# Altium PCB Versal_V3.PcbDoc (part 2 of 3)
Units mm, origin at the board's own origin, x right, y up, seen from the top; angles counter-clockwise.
Board outline 164.5 x 88.9 mm, 8 copper layers (Top Layer, Layer 2 [GND], Layer 3 [GND/OUT], Layer 4 [12V/GND], Layer 5 [GND/VOUT], Layer 6 [GND], Layer 7 [GND], Bottom Layer), stack 1.562 mm thick; 243 components, 69 nets, 695 pads, 1061 vias.
Unrouted connection lines stored in the file: 8.
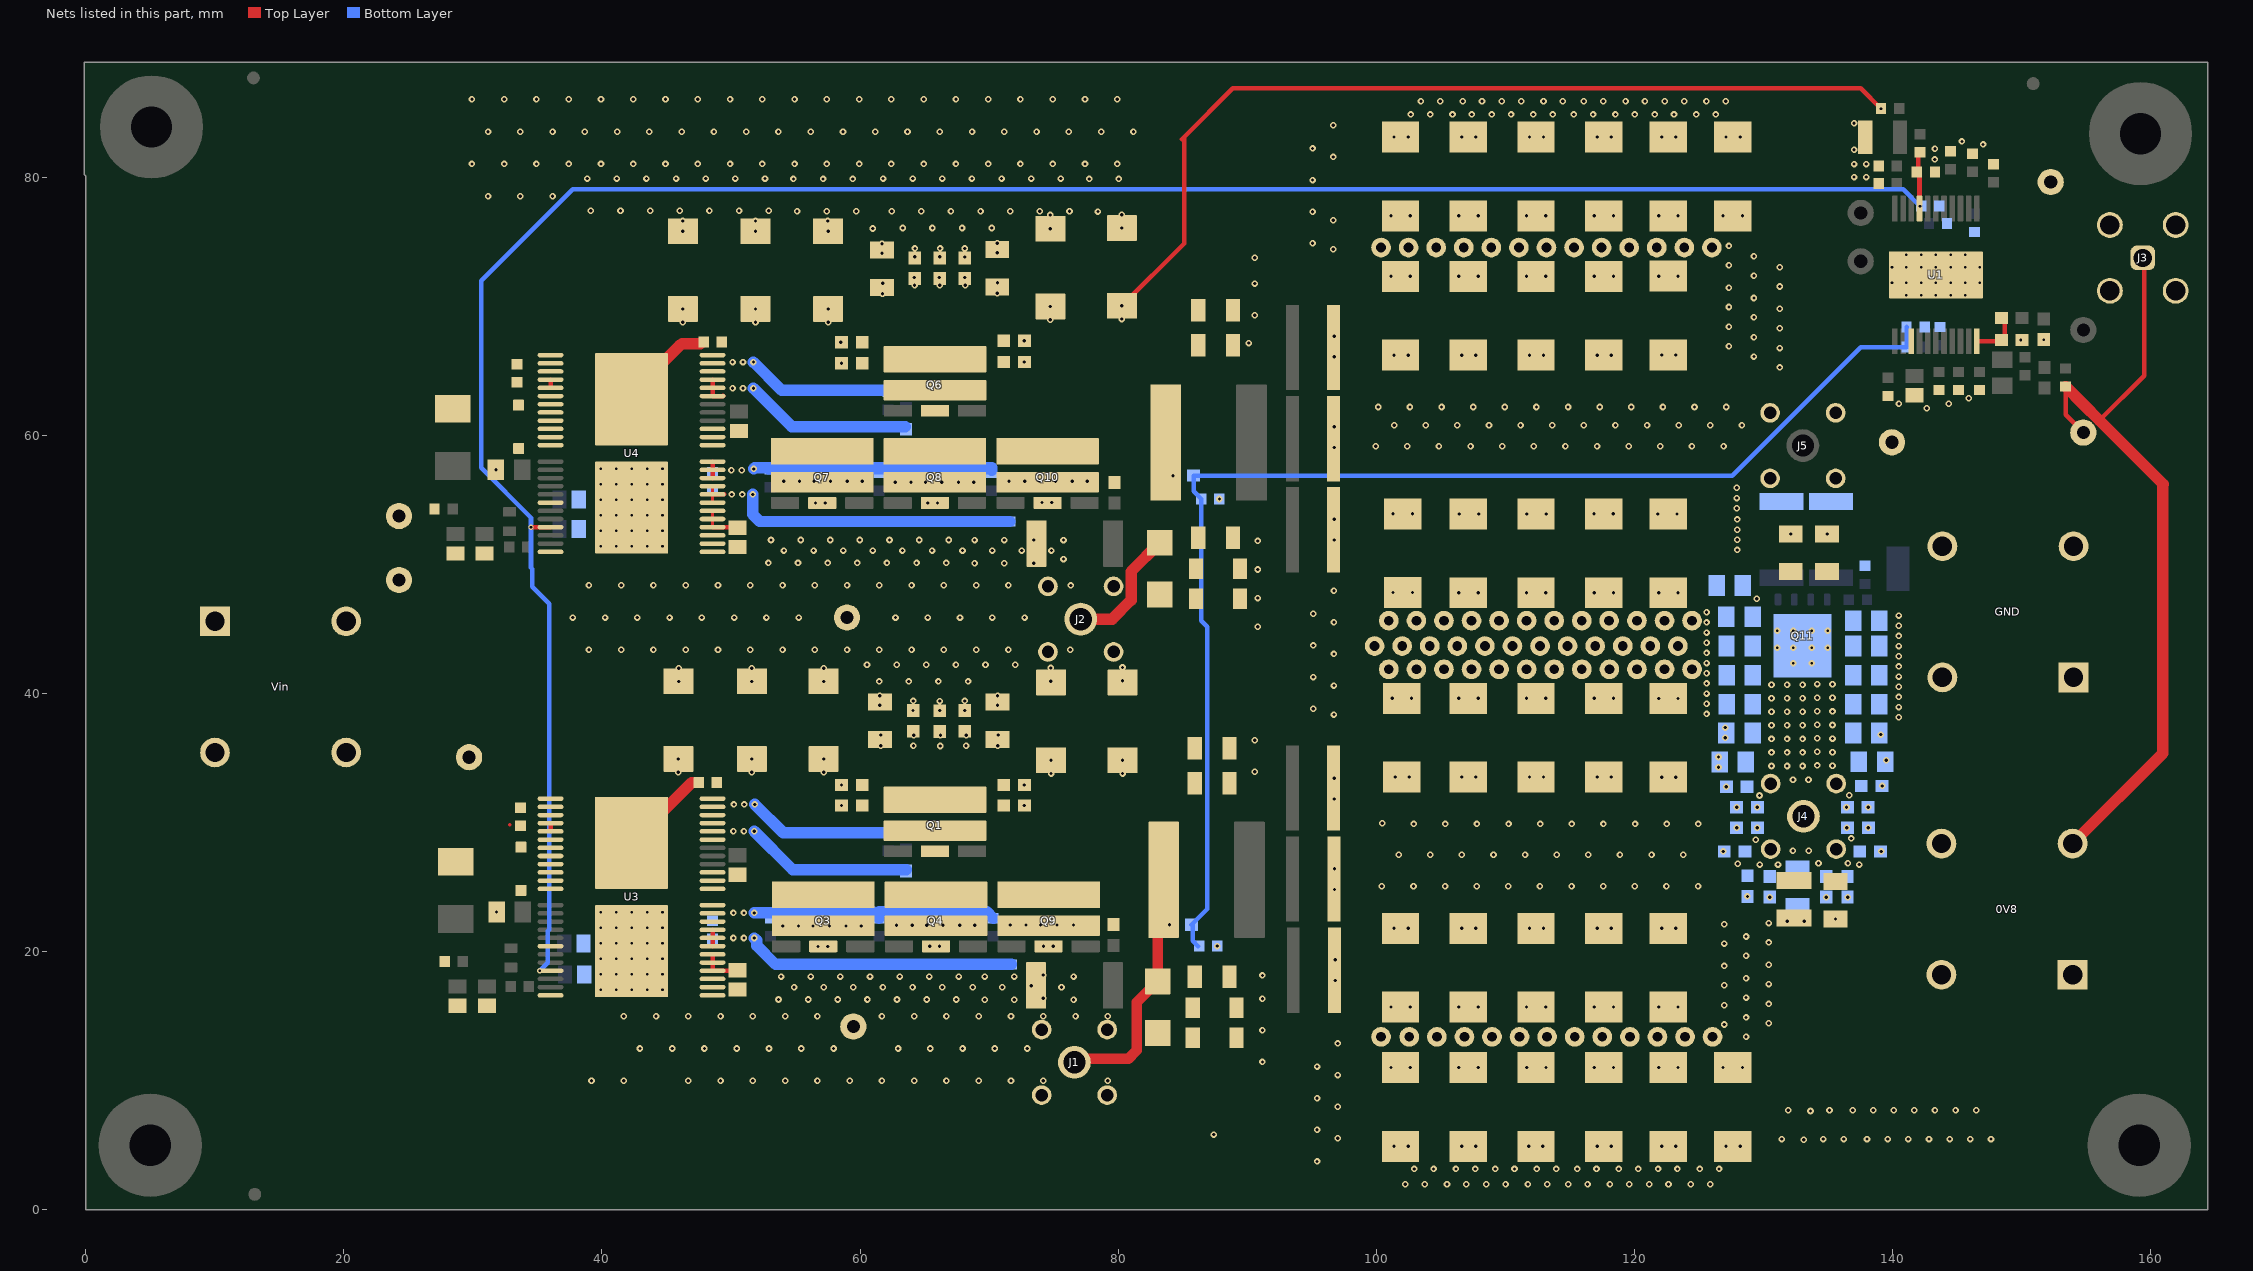
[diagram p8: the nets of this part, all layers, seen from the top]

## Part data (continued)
C14 C15 C123 C124 C125 C126 C127 C128: library part CMP-0084679-1, "CAP, CERM, 0.1 µF, 25 V,+/- 10%, X7R, AEC-Q200 Grade 1, 0603", Cap_Case=0603, Manufacturer=MuRata, TempCo=X7R, Tolerance_%=10%, Value2=25V, ValueDisplayed=0.1µF
C16: library part CMP-0081783-1, "CAP, CERM, 22 µF, 16 V,+/- 10%, X7R, 1210", Cap_Case=1210, Manufacturer=Samsung, Supplier Part Number 1=1276-3394-1-ND, TempCo=X7R, Tolerance_%=10%, Value2=16V, ValueDisplayed=22µF
C17 C23 C30 C32: library part CMP-0008687-2, "CAP, CERM, 10 uF, 10 V, +/- 10%, X7R, 1206", Cap_Case=1206, Manufacturer=TDK, Supplier Part Number 1=445-14793-1-ND, TempCo=X7R, Tolerance_%=10%, Value1="0.002454 ohm", Value2=10V, ValueDisplayed=10uF
C18 C20 C21 C24 C25 C27 C28 C31: library part CMP-0083705-1, "CAP, CERM, 1 µF, 50 V,+/- 10%, X7R, AEC-Q200 Grade 1, 0805", Cap_Case=0805, Manufacturer=AVX, Supplier Part Number 1=478-9557-1-ND, TempCo=X7R, Tolerance_%=10%, Value2=50V, ValueDisplayed=1µF
C19 C26: library part CMP-0007977-2, "CAP, CERM, 2.2 uF, 50 V, +/- 10%, X7R, AEC-Q200 Grade 1, 0805", Cap_Case=0805, Manufacturer=TDK, Supplier Part Number 1=445-174216-1-ND, TempCo=X7R, Tolerance_%=10%, Value1="0.003288 ohm", Value2=50V, ValueDisplayed=2.2uF
C33 C34 C35 C36: library part CMP-0007690-2, "CAP, CERM, 4.7 uF, 10 V, +/- 10%, X7R, 0805", Cap_Case=0805, Manufacturer="Wurth Elektronik", Supplier Part Number 1=710-885012207025, TempCo=X7R, Tolerance_%=10%, Value1=Unknown, Value2=10V, ValueDisplayed=4.7uF
C37 C38 C39: library part CMP-0008317-2, "CAP, CERM, 2.2 uF, 10 V, +/- 10%, X7R, 0805", Cap_Case=0805, Manufacturer=MuRata, Supplier Part Number 1=490-1696-1-ND, TempCo=X7R, Tolerance_%=10%, Value1="0.006 ohm", Value2=10V, ValueDisplayed=2.2uF
C40 C41 C42 C43 C44 C45 C46 C47 C48 C49 C50 C76 C90 C91 C92 C93 C94 C95 C96 C97 C98 C99 C100 C101 C102 C103 C104 C105 C106 C107 C108 C109: library part CMP-0012619-3, "CAP, Tantalum Polymer, 1500 uF, 2.5 V, +/- 20%, 0.015 ohm, 7343-40 SMD", Cap_Case=D4, Manufacturer=Panasonic, Supplier Part Number 1=P16537CT-ND, Tolerance_%=20%, Value1="0.015 ohm", Value2=2.5V, ValueDisplayed=1500uF
C51 C52 C53 C54 C65 C77: library part CMP-0079630-1, "CAP, CERM, 1 µF, 16 V,+/- 10%, X7R, AEC-Q200 Grade 1, 0805", Cap_Case=0805, Manufacturer=Kemet, Supplier Part Number 1=399-6930-1-ND, TempCo=X7R, Tolerance_%=10%, Value2=16V, ValueDisplayed=1µF
C55 C57 C58 C61 C62 C63: library part CMP-0006724-5, "CAP, CERM, 1000 pF, 100 V, +/- 10%, X7R, 0603", Cap_Case=0603, Manufacturer=AVX, Supplier Part Number 1=478-1199-1-ND, TempCo=X7R, Tolerance_%=10%, Value1="0.276 ohm", Value2=100V, ValueDisplayed=1000pF
C56 C59 C60 C64 C78 C83: library part CMP-0008483-2, "CAP, CERM, 1000 pF, 100 V, +/- 10%, X7R, 1206", Cap_Case=1206, Manufacturer=AVX, Supplier Part Number 1=478-1517-1-ND, TempCo=X7R, Tolerance_%=10%, Value1="0.427 ohm", Value2=100V, ValueDisplayed=1000pF
C66 C67 C68 C69 C70 C71 C72 C73 C74 C75: library part CMP-0095928-1, "220 µF Molded Tantalum Polymer Capacitor 16 V 2917 (7343 Metric) 40mOhm @ 100kHz", Digikey Part Number=399-8555-1-ND, Leakage Current=352uA, Manufacturer=Kemet, Mouser Part Number=80-T541X227M16AH6710, Operating Temperature Range="-55°C to +125°C", Tolerance_%=20%, ValueDisplayed=220uF
C79 C80 C84 C85: library part CMP-0008583-2, "CAP, CERM, 0.01 uF, 250 V, +/- 10%, X7R, 1206", Cap_Case=1206, Manufacturer=Kemet, Supplier Part Number 1=399-4671-1-ND, TempCo=X7R, Tolerance_%=10%, Value1=Unknown, Value2=250V, ValueDisplayed=0.01uF
C81 C82 C86 C87: library part CMP-0008973-2, "CAP, CERM, 0.1 uF, 250 V, +/- 10%, X7R, 1206", Cap_Case=1206, Manufacturer=MuRata, Supplier Part Number 1=490-3542-1-ND, TempCo=X7R, Tolerance_%=10%, Value1=Unknown, Value2=250V, ValueDisplayed=0.1uF
C88 C112 C113 C114 C115 C116: library part CMP-0006946-4, "CAP, CERM, 0.47 uF, 10 V, +/- 10%, X7R, 0603", Cap_Case=0603, Manufacturer=Kemet, Supplier Part Number 1=399-4923-1-ND, TempCo=X7R, Tolerance_%=10%, Value1=Unknown, Value2=10V, ValueDisplayed=0.47uF
C89: library part CMP-0007601-2, "CAP, CERM, 2200 pF, 50 V, +/- 5%, C0G/NP0, 0805", Cap_Case=0805, Manufacturer=AVX, Supplier Part Number 1=478-1330-1-ND, TempCo=C0G/NP0, Tolerance_%=5%, Value1="0.08 ohm", Value2=50V, ValueDisplayed=2200pF
C110 C111: library part CMP-0006814-5, "CAP, CERM, 0.01 uF, 10 V, +/- 10%, X7R, 0603", Cap_Case=0603, Manufacturer=AVX, Supplier Part Number 1=478-7938-2-ND, TempCo=X7R, Tolerance_%=10%, Value1=Unknown, Value2=10V, ValueDisplayed=0.01uF
C117 C118 C119 C120 C121 C122: library part CMP-0064931-4, "CAP, CERM, 0.1 uF, 10 V,+/- 10%, X7R, 0603", Cap_Case=0603, Manufacturer="Wurth Elektronik", Supplier Part Number 1=732-7939-1-ND, TempCo=X7R, Tolerance_%=10%, Value1=Unknown, Value2=10V, ValueDisplayed=0.1uF
D1 D5: library part CMP-0076963-2, "Diode, Superfast Rectifier, 50 V, 3 A, SMB", Manufacturer="Diodes Inc.", Value1=3A, Value2=0.9V
D2 D6: library part CMP-0124121-1, "Diode Zener Single 13V 500mW 2-Pin SOD-123 T/R", Digikey Part Number=112-BZT52B13-E3-08CT-ND, Manufacturer=Vishay, Max Reverse Leakage Current=0.1uA, Mouser Part Number=78-BZT52B13-E3-08, Operating Temperature Range="-55°C to +150°C", Power_W=300mW
D7 D8: library part CMP-0090591-1, "Diode Schottky 40V 3A Surface Mount SMA", Digikey Part Number=NRVBA340T3GOSCT-ND, Forward Current=3A, Manufacturer="ON Semiconductor", Max Surge Forward Current=100A, Mouser Part Number=863-NRVBA340T3G, Operating Temperature Range="-55°C to +150°C", Part Number=NRVBA340T3G, Peak Reverse Current=0.3mA
FID1 FID2 FID3: library part CMP-0077181-1, "Fiducial mark.  There is nothing to buy or mount.", Manufacturer=N/A
GND1 GND2 GND3 GND4 GND5: library part CMP-0055138-2, "Test Point, Miniature, Black, TH", Color=Black, Manufacturer="Keystone Electronics", PartNumber=5001, Supplier Part Number 1=36-5001-ND
H1 H2 H3 H4: library part CMP-0003617-1, "Machine Screw, Round, #4-40 x 1/4, Nylon, Philips panhead", Manufacturer="B&F Fastener Supply", Supplier Part Number 1=H542-ND
H5 H6 H7 H8: library part CMP-0003610-1, "Standoff, Hex, 0.5\"L #4-40 Nylon", Manufacturer=Keystone, Supplier Part Number 1=36-1902C-ND
J1 J2 J4 J5: library part CMP-0055433-1, "Compact Probe Tip Circuit Board Test Points, TH, 25 per", Manufacturer=Tektronix, PartNumber=131-5031-00, Supplier Part Number 1=11B2822
J3: library part CMP-0055850-1, "JACK, SMA, 50 Ohm, Gold, R/A, TH", Manufacturer="Linx Technologies", Supplier Part Number 1=CONSMA002-G-ND
L1 L2: library part CMP-0090776-1, "Shielded Power Inductors - XAL1010 0.45uH AEC Q-200 20% 0.72mohm SRF: 66MHz 40A", Manufacturer=Coilcraft, Mouser Part Number=994-XAL1010-451MEB, Operating Temperature Range="to +165°C", Self Resonant Frequency=66MHz, Test Frequency=1MHz, Tolerance_%=20%
LBL1: library part CMP-0003625-1, Manufacturer=Brady, Supplier Part Number 1=97C5133
Logo1: library part CMP-0074837-2, "IEC 61010-1 Hot Surface Warning", Manufacturer="Texas Instruments"
Logo3: library part CMP-0074847-1, "FCC_disclaimer"
Logo4: library part CMP-0074769-3, Manufacturer="Texas Instruments"
Logo5: library part CMP-0074836-1, "IEC 61010-1 Caution Warning"
Q1 Q3 Q4 Q6 Q7 Q8 Q9 Q10: library part CMP-0044865-1, "MOSFET N-Channel 40 V 80A (Tc) Surface Mount 5-SMD", Digikey Part Number=4107-EPC7019GC-ND, Drain To Source Breakdown Voltage=40V, Input Capacitace At Vds="2830pF @ 20V", Manufacturer="EPC Space", Operating Temperature Range="-55°C to +150°C", Pulse Drain Current=530A
Q11: library part CMP-0000264-1, "MOSFET, N-CH, 25 V, 113 A, DQH0008A (VSON-CLIP-8)", Alternate Manufacturer=None, Manufacturer="Texas Instruments", Supplier Part Number 1=296-25321-1-ND, Value1=0.005, Value2="6.7 nC"
R1 R5 R12 R14 R18 R24 R46 R71 R74 R75 R76 R77 R78 R79 R84 R87 R88 R89 R90 R91 R92: library part CMP-0023343-3, "RES, 0, 1%, 0.1 W, AEC-Q200 Grade 0, 0603", Manufacturer="Stackpole Electronics Inc", Power_W=100mW, Supplier Part Number 1=RMCF0603ZT0R00CT-ND, TempCo=ppm/C, Tolerance_%=1%, Value2=0.1W, Value_Code=0
R2: library part CMP-0023142-5, "RES, 49.9 k, 1%, 0.1 W, 0603", Manufacturer=Yageo, Power_W=100mW, Supplier Part Number 1=311-49.9KHRCT-ND, TempCo="100 ppm/C", Tolerance_%=1%, Value2=0.1W, Value_Code=49k9, ValueDisplayed=49.9k
R3: library part CMP-0022751-4, "RES, 10.0, 1%, 0.1 W, 0603", Manufacturer=Yageo, Power_W=100mW, Supplier Part Number 1=311-10.0HRCT-ND, TempCo="100 ppm/C", Tolerance_%=1%, Value2=0.1W, Value_Code=10R0, ValueDisplayed=10.0
R4: library part CMP-0023143-5, "RES, 49.9, 1%, 0.1 W, 0603", Manufacturer=Yageo, Power_W=100mW, Supplier Part Number 1=311-49.9HRCT-ND, TempCo="100 ppm/C", Tolerance_%=1%, Value2=0.1W, Value_Code=49R9, ValueDisplayed=49.9
R6: library part CMP-0023077-5, "RES, 3.09 k, 1%, 0.1 W, 0603", Manufacturer=Yageo, Power_W=100mW, Supplier Part Number 1=311-3.09KHRCT-ND, TempCo="100 ppm/C", Tolerance_%=1%, Value2=0.1W, Value_Code=3k09, ValueDisplayed=3.09k
R7: library part CMP-0023404-3, "RES, 10.0 k, 0.1%, 0.1 W, 0603", Manufacturer="Susumu Co Ltd", Power_W=100mW, Supplier Part Number 1=RG16P10.0KBCT-ND, TempCo="25 ppm/C", Tolerance_%=0.1%, Value2=0.1W, Value_Code=10k0, ValueDisplayed=10.0k
R8: library part CMP-0023070-4, "RES, 392 k, 1%, 0.1 W, 0603", Manufacturer=Yageo, Power_W=100mW, Supplier Part Number 1=311-392KHRCT-ND, TempCo="100 ppm/C", Tolerance_%=1%, Value2=0.1W, Value_Code=392k
R9: library part CMP-0022098-4, "RES, 18.7 k, 1%, 0.1 W, AEC-Q200 Grade 0, 0603", Manufacturer=Vishay-Dale, Power_W=100mW, Supplier Part Number 1=541-18.7KHCT-ND, TempCo="100 ppm/C", Tolerance_%=1%, Value2=0.1W, Value_Code=18k7, ValueDisplayed=18.7k
R10: library part CMP-0023517-2, "RES, 33.2 k, 0.1%, 0.1 W, 0603", Manufacturer="Susumu Co Ltd", Power_W=100mW, Supplier Part Number 1=RG16P33.2KBCT-ND, TempCo="25 ppm/C", Tolerance_%=0.1%, Value2=0.1W, Value_Code=33k2, ValueDisplayed=33.2k
R11 R13: library part CMP-0025332-2, "RES, 49.9 k, 0.5%, 0.1 W, 0603", Manufacturer="Yageo America", Power_W=100mW, TempCo="50 ppm/C", Tolerance_%=0.5%, Value2=0.1W, Value_Code=49k9, ValueDisplayed=49.9k
R15 R16 R19 R20: library part CMP-0020063-2, "RES, 41.2 k, 0.1%, 0.125 W, 0805", Manufacturer="Yageo America", Power_W=125mW, TempCo="25 ppm/C", Tolerance_%=0.1%, Value2=0.125W, Value_Code=41k2, ValueDisplayed=41.2k
R17 R21: library part CMP-0023899-3, "RES, 1.50 k, 0.1%, 0.1 W, 0603", Manufacturer="Yageo America", Power_W=100mW, TempCo="25 ppm/C", Tolerance_%=0.1%, Value2=0.1W, Value_Code=1k50, ValueDisplayed=1.50k
R23 R45: library part CMP-0096593-1, "2 Ohms ±1% 0.25W, 1/4W Chip Resistor 0603 (1608 Metric) Automotive AEC-Q200, Pulse Withstanding Thick Film", Digikey Part Number=541-10451-1-ND, Manufacturer="Vishay Dale", Mouser Part Number=71-RCS06032R00FKEA, Operating Temperature Range="-55°C to +155°C", Power_W=250mW, TempCo=100ppm/°C, Tolerance_%=1%
R28 R29 R30 R31 R32 R33: library part CMP-0015108-2, "RES, 0.007, 1%, 3 W, 2512 WIDE", Manufacturer="Susumu Co Ltd", Power_W=3W, Supplier Part Number 1=408-1617-1-ND, TempCo="50 ppm/C", Tolerance_%=1%, Value_Code=7L000, ValueDisplayed=0.007
R67: library part CMP-0024533-3, "RES, 931, 0.1%, 0.1 W, 0603", Manufacturer="Yageo America", Power_W=100mW, TempCo="25 ppm/C", Tolerance_%=0.1%, Value2=0.1W, Value_Code=931R, ValueDisplayed=931
R68 R69 R81 R82: library part CMP-0023337-3, "RES, 10.0 k, 1%, 0.1 W, 0603", Manufacturer="Vishay Draloric", Power_W=100mW, Supplier Part Number 1=541-1784-1-ND, TempCo="100 ppm/C", Tolerance_%=1%, Value2=0.1W, Value_Code=10k0, ValueDisplayed=10.0k
R70 R83: library part CMP-0025804-4, "RES, 3.0, 5%, 0.1 W, AEC-Q200 Grade 0, 0603", Manufacturer=Vishay-Dale, Power_W=100mW, Supplier Part Number 1=541-3.0GCT-ND, TempCo="200 ppm/C", Tolerance_%=5%, Value2=0.1W, Value_Code=3R00, ValueDisplayed=3.0
R94: library part CMP-0081973-1, "RES, 0, 0%, 0.25 W, AEC-Q200 Grade 0, 0603", Manufacturer=Vishay-Dale, Power_W=250mW, Supplier Part Number 1=541-2779-1-ND, Tolerance_%=0%, Value2=0.25W, Value_Code=0
R95: library part CMP-0023392-3, "RES, 10.0 k, 0.1%, 0.0375 W, 0603", Manufacturer="Vishay Sfernice", Power_W=37.5mW, Supplier Part Number 1=PHTB-10KCT-ND, TempCo="15 ppm/C", Tolerance_%=0.1%, Value2=0.0375W, Value_Code=10k0, ValueDisplayed=10.0k
R96 R97: library part CMP-0015854-2, "RES, 0.04, 1%, 2 W, AEC-Q200 Grade 0, 2512", Manufacturer=Vishay-Dale, Power_W=2W, Supplier Part Number 1=WSLH-.04CT-ND, TempCo="75 ppm/C", Tolerance_%=1%, Value_Code=R040, ValueDisplayed=0.04
R99: library part CMP-0022899-4, "RES, 1.00 M, 1%, 0.1 W, 0603", Manufacturer=Yageo, Power_W=100mW, Supplier Part Number 1=311-1.00MHRCT-ND, TempCo="100 ppm/C", Tolerance_%=1%, Value2=0.1W, Value_Code=1M00, ValueDisplayed=1.00M
R100 R101: library part CMP-0123586-1, "500 mOhms ±1% 4W Chip Resistor 2512 (6432 Metric) Automotive AEC-Q200, Current Sense, Moisture Resistant, Pulse Withstanding Metal Foil", Digikey Part Number=4423-VMS-R500-1.0-UCT-ND, Manufacturer=Isabellenhuette, Operating Temperature Range="-65°C to +170°C", Power_W=4W, TempCo=20ppm/°C, Tolerance_%=1%
TP3 TP4 TP5: library part CMP-0055139-1, "Test Point, Miniature, White, TH", Color=White, Manufacturer=Keystone, PartNumber=5002, Supplier Part Number 1=36-5002-ND
TP7 TP8 TP10: library part CMP-0055137-2, "Test Point, Miniature, Red, TH", Color=Red, Manufacturer="Keystone Electronics", PartNumber=5000, Supplier Part Number 1=36-5000-ND
TP13: library part CMP-0055152-2, "Test Point, Miniature, SMT", Manufacturer="Keystone Electronics", PartNumber=5015, Supplier Part Number 1=36-5015TR-ND
U1: library part CMP-0094374-1, "Radiation-Hardness-Assured Current Mode PWM Controllers", Manufacturer="Texas Instruments", Max Supply Voltage=14V, Min Supply Voltage=4V, Nominal Supply Current=6.25-14mA, Operating Temperature Range="-55°C to +125°C", Switching Frequency=100-2000kHz
U3 U4: library part CMP-0096403-3, "Radiation-Hardness-Assured 200-V, 1.5-A 3-A, Half Bridge GaN FET Gate Driver", Manufacturer="Texas Instruments", Max Supply Voltage=14V, Min Supply Voltage=10V, Operating Temperature Range="-55°C to +125°C", Part Number=TPS7H6003/EM
Vin: library part CMP-0078537-1, "Fixed Terminal Blocks MKDSP 10 HV/ 2-10", Current_A=76A, Manufacturer="Phoenix Contact", PartNumber=1929517, Voltage_V=1kV

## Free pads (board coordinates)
  round 1.524 hole 0.762: 2(99.862,43.68) 2(100.359,13.405) 2(100.359,74.556) 2(100.961,41.88) 2(100.961,45.646) 2(101.998,43.68) 2(102.496,74.556) 2(102.549,13.405) 2(103.097,41.88) 2(103.097,45.646) 2(104.134,43.68) 2(104.632,74.556) 2(104.685,13.405) 2(105.233,41.88) 2(105.233,45.646) 2(106.27,43.68) 2(106.768,74.556) 2(106.821,13.405) 2(107.369,41.88) 2(107.369,45.646) 2(108.407,43.68) 2(108.904,74.556) 2(108.957,13.405) 2(109.506,41.88) 2(109.506,45.646) 2(110.543,43.68) 2(111.041,74.556) 2(111.093,13.405) 2(111.642,41.88) 2(111.642,45.646) 2(112.679,43.68) 2(113.177,74.556) 2(113.23,13.405) 2(113.778,41.88) 2(113.778,45.646) 2(114.815,43.68) 2(115.313,74.556) 2(115.366,13.405) 2(115.914,41.88) 2(115.914,45.646) 2(116.952,43.68) 2(117.449,74.556) 2(117.502,13.405) 2(118.03,45.646) 2(118.05,41.88) 2(119.088,43.68) 2(119.585,74.556) 2(119.638,13.405) 2(120.187,41.88) 2(120.187,45.646) 2(121.224,43.68) 2(121.722,74.556) 2(121.775,13.405) 2(122.323,41.88) 2(122.323,45.646) 2(123.36,43.68) 2(123.858,74.556) 2(123.911,13.405) 2(124.459,41.88) 2(124.459,45.646) 2(125.994,74.556) 2(126.047,13.405)

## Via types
v1: diameter 0.508, hole 0.254, Top Layer to Bottom Layer, 951 vias
v2: diameter 0.5, hole 0.2, Top Layer to Bottom Layer, tented both sides, 60 vias
v3: diameter 0.5, hole 0.2, Top Layer to Bottom Layer, 34 vias
v4: diameter 0.406, hole 0.203, Top Layer to Bottom Layer, 16 vias

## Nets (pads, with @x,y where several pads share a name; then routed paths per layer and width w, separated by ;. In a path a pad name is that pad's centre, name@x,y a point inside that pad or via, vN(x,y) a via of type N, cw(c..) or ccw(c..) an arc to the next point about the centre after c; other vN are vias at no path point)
0V8: 0V8.1 0V8.2 C12.1 C13.1 C16.1 C17.1 C23.1 C30.1 C32.1 C33.1 C34.1 C35.1 C36.1 C37.1 C38.1 C39.1 C40.1 C41.1 C42.1 C43.1 C44.1 C45.1 C46.1 C47.1 C48.1 C49.1 C50.1 C51.1 C52.1 C53.1 C54.1 C65.1 C76.1 C77.1 C78.1 C79.1 C80.1 C81.1 C82.1 C83.1 C84.1 C85.1 C86.1 C87.1 C88.1 C90.1 C91.1 C92.1 C93.1 C94.1 C95.1 C96.1 C97.1 C98.1 C99.1 C100.1 C101.1 C102.1 C103.1 C104.1 C105.1 C106.1 C107.1 C108.1 C109.1 C112.1 C113.1 C114.1 C115.1 C116.1 C117.1 C118.1 C119.1 C120.1 C121.1 C122.1 J3.1 J4.1 Q11.5 Q11.6 Q11.7 Q11.8 Q11.9@133.019,43.7 R4.2 R28.2 R29.2 R30.2 R31.2 R32.2 R33.2 TP7.1 | length 59.9
  Top Layer w0.356: R4.2@153.4,63.786 153.4,61.586 TP7.1@154.771,60.215 ; 156.023,61.164 159.481,64.622 159.481,73.649 J3.1@159.377,73.754 ; 160.936,56.16 160.981,56.205
  Top Layer w0.889: R4.2@153.4,63.786 154.771,62.416 156.023,61.164 160.981,56.205 ; 0V8.2@153.94,28.38 160.936,35.376 160.936,56.16
  Bottom Layer w0.889: J4.1@132.974,30.372 J4.1@133.087,30.486 J4.1@133.019,30.554
  other v1: 102.241,1.977 103.741,1.977 105.472,1.977 106.972,1.977 108.51,1.977 110.01,1.977 111.74,1.977 113.24,1.977 114.864,1.977 116.364,1.977 118.095,1.977 119.595,1.977 121.133,1.977 122.633,1.977 124.364,1.977 125.864,1.977 102.93,3.171 104.43,3.171 106.161,3.171 107.661,3.171 109.199,3.171 110.699,3.171 112.429,3.171 113.929,3.171 115.553,3.171 117.053,3.171 118.784,3.171 120.284,3.171 121.822,3.171 123.322,3.171 125.053,3.171 126.553,3.171 95.407,3.752 101.37,4.92 102.458,4.92 106.619,4.92 107.707,4.92 111.802,4.92 112.89,4.92 117.116,4.92 118.204,4.92 122.112,4.92 123.201,4.92 127.095,4.92 128.184,4.92 133.118,5.427 131.409,5.482 134.611,5.482 136.213,5.482 138.009,5.482 139.611,5.482 141.212,5.482 142.814,5.482 144.415,5.482 146.016,5.482 147.618,5.482 97.004,5.544 95.407,6.202 133.633,7.659 131.917,7.714 135.107,7.714 136.897,7.714 138.492,7.714 140.087,7.714 141.682,7.714 143.277,7.714 144.872,7.714 146.467,7.714 97.004,7.994 95.407,8.652 97.004,10.444 95.407,11.102 91.173,11.459 97.004,12.893 91.173,13.909 91.173,16.358 96.81,17.773 91.173,18.161 96.81,19.38 87.677,20.436 101.37,21.81 102.458,21.81 106.619,21.81 107.707,21.81 111.867,21.81 112.956,21.81 117.116,21.81 118.204,21.81 122.112,21.81 123.201,21.81 96.76,24.821 100.424,25.08 102.874,25.08 105.324,25.08 107.774,25.08 110.223,25.08 112.673,25.08 115.123,25.08 117.573,25.08 120.023,25.08 122.473,25.08 124.923,25.08 96.76,26.428 129.706,26.753 131.114,26.753 137.411,26.753 127.989,26.823 134.253,26.844 136.532,26.844 101.722,27.506 104.172,27.506 106.622,27.506 109.072,27.506 111.522,27.506 113.972,27.506 116.422,27.506 118.871,27.506 121.321,27.506 123.771,27.506 132.274,27.819 133.506,27.819 129.396,28.671 136.781,28.777 129.514,29.601 136.439,29.601 102.893,29.898 105.342,29.898 107.792,29.898 110.242,29.898 112.692,29.898 115.142,29.898 117.592,29.898 120.042,29.898 122.492,29.898 124.941,29.898 100.464,29.951 129.514,31.184 136.423,31.184 96.742,31.835 129.683,32.101 136.647,32.111 132.277,33.318 133.477,33.318 96.742,33.442 101.458,33.534 102.547,33.534 106.619,33.534 107.707,33.534 111.867,33.534 112.956,33.534 117.116,33.534 118.204,33.534 122.112,33.524 123.201,33.524 90.58,33.933 130.614,34.386 131.817,34.386 133.017,34.386 135.338,34.412 134.162,34.432 130.614,35.437 131.817,35.437 133.017,35.437 135.338,35.463 134.162,35.483 90.58,36.383 130.614,36.487 131.817,36.487 133.017,36.487 134.162,36.533 135.338,36.513 130.614,37.538 131.817,37.538 133.017,37.538 135.338,37.564 134.162,37.584 96.71,38.37 130.614,38.588 131.817,38.588 133.017,38.588 135.338,38.614 134.162,38.634 95.113,38.827 130.614,39.639 131.817,39.639 133.017,39.639 134.162,39.685 135.338,39.665 96.71,40.619 130.614,40.689 131.817,40.689 133.017,40.689 135.338,40.715 134.162,40.735 95.113,41.277 96.71,43.069 95.113,43.727 90.818,45.181 96.71,45.518 95.113,46.177 129.478,47.352 90.818,47.396 96.71,47.968 90.818,49.612 90.818,51.827 96.742,51.893 96.742,53.5 106.422,53.91 107.922,53.91 111.655,53.91 113.155,53.91 121.791,53.91 123.291,53.91 101.295,53.927 102.795,53.927 116.857,53.929 118.357,53.929 87.837,55.074 96.742,59.069 99.948,59.16 102.397,59.16 104.847,59.16 107.297,59.16 109.747,59.16 112.197,59.16 114.647,59.16 117.097,59.16 119.547,59.16 121.996,59.16 124.446,59.16 126.896,59.16 96.742,60.676 101.374,60.78 103.824,60.78 106.274,60.78 108.723,60.78 111.173,60.78 113.623,60.78 116.073,60.78 118.523,60.78 120.973,60.78 123.423,60.78 125.873,60.78 128.322,60.78 100.15,62.201 102.6,62.201 105.049,62.201 107.499,62.201 109.949,62.201 112.399,62.201 114.849,62.201 117.299,62.201 119.749,62.201 122.199,62.201 124.648,62.201 127.098,62.201 96.742,66.084 101.37,66.221 102.458,66.221 106.619,66.221 107.707,66.221 111.867,66.221 112.956,66.221 117.116,66.221 118.204,66.221 122.112,66.236 123.201,66.236 90.121,67.152 96.742,67.691 90.578,69.316 90.578,71.766 90.578,73.757 96.651,74.426 95.054,74.883 96.651,76.675 95.054,77.333 95.054,79.783 96.651,81.574 95.054,82.232 101.37,83.118 102.458,83.118 106.619,83.118 107.707,83.118 111.867,83.118 112.956,83.118 117.116,83.118 118.204,83.118 122.112,83.118 123.201,83.118 127.095,83.118 128.184,83.118 96.651,84.024 102.664,84.867 104.164,84.867 105.895,84.867 107.395,84.867 108.933,84.867 110.433,84.867 112.164,84.867 113.664,84.867 115.288,84.867 116.788,84.867 118.519,84.867 120.019,84.867 121.557,84.867 123.057,84.867 124.787,84.867 126.287,84.867 103.45,85.885 104.95,85.885 106.68,85.885 108.18,85.885 109.718,85.885 111.218,85.885 112.949,85.885 114.449,85.885 116.073,85.885 117.573,85.885 119.304,85.885 120.804,85.885 122.342,85.885 123.842,85.885 125.573,85.885 127.073,85.885
  other v3: 132.304,42.346 133.734,42.346 131.059,43.536 132.304,43.536 133.734,43.536 134.979,43.536 131.059,44.876 132.304,44.876 133.734,44.876 134.979,44.876
12V: C14.1 C15.1 C55.1 C56.1 C57.1 C58.1 C59.1 C60.1 C61.1 C62.1 C63.1 C64.1 C66.2 C67.2 C68.2 C69.2 C70.2 C71.2 C72.2 C73.2 C74.2 C75.2 C123.1 C124.1 C125.1 C126.1 C127.1 C128.1 Q1.3 Q6.3 R1.1 R24.2 R46.2 TP8.1 TP10.1 Vin.2 | length 71.5
  Top Layer w0.356: v1(80.279,70.045) 85.105,74.871 85.105,83.119 ; 84.94,82.954 85.105,83.119 ; v4(139.099,85.322) 137.524,86.896 88.883,86.896 85.105,83.119
  other v1: 74.796,33.806 80.334,33.806 45.919,33.904 51.614,33.904 57.174,33.904 74.796,34.838 80.334,34.838 45.919,34.936 51.614,34.936 57.174,34.936 64.13,35.948 66.204,35.937 68.207,35.948 61.59,35.961 70.674,35.961 61.609,36.79 64.149,36.778 66.223,36.767 68.225,36.778 70.693,36.79 46.268,68.769 51.896,68.769 57.523,68.769 74.74,68.963 80.279,69.013 46.268,69.801 51.896,69.801 57.523,69.801 74.74,69.995 61.733,70.971 70.626,71.006 64.222,71.633 66.166,71.633 68.144,71.633 61.752,71.8 70.644,71.836 64.193,72.24 66.138,72.239 68.116,72.235
ASW1: C21.2 C22.2 C111.1 D2.1 D7.1 J1.1 L1.1 Q1.4 Q1.5 Q3.3 Q4.3 Q9.3 R17.1 R68.1 U3.1 U3.2 U3.3 U3.6 U3.7 U3.8 U3.9 U3.10 U3.11 U3.12 U3.37 U3.38 U3.39 U3.49 | length 26.4
  Top Layer w0.356: 46.958,33.1 R68.1@47.5,33.1 ; L1.1@83.059,25.112 L1.1@83.515,25.568
  Top Layer w0.813: J1.1@76.606,11.426 76.867,11.687 80.777,11.687 81.45,12.359 81.45,16.091 D7.1@83.059,17.701 L1.1@83.059,25.112
  Top Layer w0.889: U3.49@42.292,28.434 46.958,33.1
  other v1: 83.977,22.095
ASW2: C28.2 C29.2 C110.1 D6.1 D8.1 J2.1 L2.1 Q6.4 Q6.5 Q7.3 Q8.3 Q10.3 R21.1 R81.1 U4.1 U4.2 U4.3 U4.6 U4.7 U4.8 U4.9 U4.10 U4.11 U4.12 U4.37 U4.38 U4.39 U4.49 | length 17.7
  Top Layer w0.889: U4.49@41.723,62.67 46.028,66.974 ; 46.21,67.104 R81.1@47.614,67.104 ; J2.1@76.736,45.766 J2.1@77.096,45.766 79.52,45.766 80.995,47.24 80.995,49.453 D8.1@83.219,51.677
  other v1: 84.237,56.885
BOOT1: C22.1 D1.1 D2.2 U3.4 U3.5 | length 0.7
  Top Layer w0.254: 32.849,29.853 32.854,29.853 32.862,29.845
  Top Layer w0.356: U3.5@36.017,29.319 U3.4@36.017,29.954
BOOT2: C29.1 D5.1 D6.2 U4.4 U4.5 | length 0.7
  Top Layer w0.254: C29.1@33.399,64.125 C29.1@33.411,64.137
  Top Layer w0.356: U4.5@36.017,63.684 U4.4@36.017,64.319
BP5L1: C24.1 U3.28 U3.29 U3.30 | length 3.2
  Top Layer w0.356: U3.30@48.567,19.794 U3.29@48.567,19.159 U3.28@48.567,18.524 50.461,18.524 C24.1@50.497,18.56
BP5L2: C31.1 U4.28 U4.29 U4.30 | length 3.3
  Top Layer w0.254: U4.28@48.567,52.889 U4.29@48.567,53.524 U4.30@48.567,54.159
  Top Layer w0.356: U4.28@48.567,52.889 50.568,52.889 C31.1@50.605,52.852
COMP: C10.1 R9.2 U1.22 | length 4
  Top Layer w0.356: U1.22@146.521,67.289 148.434,67.289 148.536,67.391 148.686,67.541 148.686,69.103 R9.2@148.536,69.103
CS1: C5.2 C12.2 C13.2 R3.2 R17.2 R21.2 | length 98.5
  Bottom Layer w0.356: R17.2@85.677,22.095 86.887,23.304 86.887,45.181 86.437,45.63 C13.2@86.437,55.074 85.837,55.674 R21.2@85.837,56.885 127.574,56.885 137.533,66.844 R3.2@141.066,66.844 141.076,66.854 C5.2@141.076,68.397 ; R17.2@85.777,22.095 85.777,20.836 C12.2@86.177,20.436
EN: C7.1 R2.1 R6.2 U1.8 U3.21 U4.21 | length 176.8
  Top Layer w0.356: v4(34.498,52.889) U4.21@36.017,52.889 ; U1.8@142.076,77.579 142.076,80.222 C7.1@141.876,80.423 141.991,80.538 141.991,81.726 R2.1@142.106,81.841
  Bottom Layer w0.356: v4(35.172,18.524) 35.794,19.146 35.794,21.602 35.904,21.712 35.904,46.957 34.587,48.274 34.587,49.653 34.498,49.742 v4(34.498,52.889) 34.498,53.624 30.642,57.481 30.642,71.979 37.733,79.07 140.814,79.07 v4(142.116,77.767)
GND: C1.2 C2.2 C3.2 C4.2 C5.1 C6.2 C7.2 C8.1 C9.1 C10.2 C11.2 C14.2 C15.2 C16.2 C17.2 C18.2 C19.2 C20.2 C23.2 C24.2 C25.2 C26.2 C27.2 C30.2 C31.2 C32.2 C33.2 C34.2 C35.2 C36.2 C37.2 C38.2 C39.2 C40.2 C41.2 C42.2 C43.2 C44.2 C45.2 C46.2 C47.2 C48.2 C49.2 C50.2 C51.2 C52.2 C53.2 C54.2 C55.2 C56.2 C57.2 C58.2 C59.2 C60.2 C61.2 C62.2 C63.2 C64.2 C65.2 C66.1 C67.1 C68.1 C69.1 C70.1 C71.1 C72.1 C73.1 C74.1 C75.1 C76.2 C77.2 C78.2 C79.2 C80.2 C81.2 C82.2 C83.2 C84.2 C85.2 C86.2 C87.2 C88.2 C90.2 C91.2 C92.2 C93.2 C94.2 C95.2 C96.2 C97.2 C98.2 C99.2 C100.2 C101.2 C102.2 C103.2 C104.2 C105.2 C106.2 C107.2 C108.2 C109.2 C112.2 C113.2 C114.2 C115.2 C116.2 C117.2 C118.2 C119.2 C120.2 C121.2 C122.2 C123.2 C124.2 C125.2 C126.2 C127.2 C128.2 D7.2 D8.2 GND1.1 GND2.1 GND3.1 GND4.1 GND5.1 GND.1 GND.2 J1.2 J1.3 J1.4 J1.5 J2.2 J2.3 J2.4 J2.5 J3.2 J3.3 J3.4 J3.5 J4.2 J4.3 J4.4 J4.5 J5.2 J5.3 J5.4 J5.5 pad.2 Q3.4 Q3.5 Q4.4 Q4.5 Q7.4 Q7.5 Q8.4 Q8.5 Q9.4 Q9.5 Q10.4 Q10.5 R5.2 R6.1 R8.2 R10.1 R11.1 R12.1 R13.1 R15.1 R16.1 R19.1 R20.1 R69.1 R82.1 R95.1 R96.1 R97.1 R99.2 R100.1 R101.1 U1.14 U1.23 U3.18 U3.24 U3.25 U3.26 U3.27 U3.50 U4.18 U4.24 U4.25 U4.26 U4.27 U4.50 Vin.1
  other v1: 87.389,5.83 39.191,10 41.691,10 46.691,10 49.191,10 51.691,10 54.191,10 56.691,10 59.191,10 61.691,10 64.191,10 66.691,10 69.191,10 71.691,10 74.191,10 79.191,10 101.133,11.02 102.633,11.02 106.381,11.02 107.881,11.02 111.649,11.02 113.149,11.02 116.879,11.02 118.379,11.02 121.875,11.02 123.375,11.02 126.858,11.02 128.358,11.02 42.941,12.5 45.441,12.5 47.941,12.5 50.441,12.5 52.941,12.5 55.441,12.5 57.941,12.5 62.941,12.5 65.441,12.5 67.941,12.5 70.441,12.5 72.941,12.5 128.641,13.408 126.949,14.359 130.395,14.45 128.641,14.908 41.691,15 44.191,15 46.691,15 49.191,15 51.691,15 54.191,15 56.691,15 61.691,15 64.191,15 66.691,15 69.191,15 71.691,15 74.191,15 76.691,15 79.191,15 101.133,15.71 102.633,15.71 106.381,15.71 107.881,15.71 111.63,15.71 113.13,15.71 116.879,15.71 118.379,15.71 121.875,15.71 123.375,15.71 126.949,15.859 130.395,15.95 69.654,16.267 71.949,16.267 76.54,16.267 53.677,16.295 55.973,16.295 58.269,16.295 60.564,16.295 62.86,16.295 65.155,16.295 67.451,16.295 74.191,16.385 128.641,16.446 54.883,17.254 57.178,17.254 59.474,17.254 61.77,17.254 64.065,17.254 66.361,17.254 68.717,17.254 71.013,17.254 75.604,17.254 73.254,17.372 126.949,17.398 130.395,17.488 128.641,17.946 53.878,18.072 56.174,18.072 58.47,18.072 60.765,18.072 63.061,18.072 65.356,18.072 67.652,18.072 69.654,18.07 71.949,18.07 76.54,18.07 74.191,18.188 126.949,18.898 130.395,18.988 128.641,19.676 56.738,20.396 57.494,20.396 65.402,20.413 66.158,20.413 74.201,20.412 74.957,20.412 126.949,20.628 130.395,20.719 128.641,21.176 54.01,21.992 55.231,21.992 56.349,21.994 57.623,21.992 58.913,21.992 60.084,21.992 62.817,22.054 64.038,22.054 65.155,22.056 66.429,22.054 67.719,22.054 68.89,22.054 71.636,22.062 72.857,22.062 73.975,22.064 75.248,22.062 76.539,22.062 126.949,22.128 130.395,22.219 131.826,22.367 133.158,22.367 135.576,22.533 31.834,23.072 130.469,24.222 134.851,24.222 136.509,24.222 128.746,24.28 126.875,27.765 139.124,27.77 127.914,29.601 138.114,29.601 127.914,31.184 138.098,31.184 72.726,31.33 58.565,31.332 127.114,32.785 139.184,32.84 58.565,32.922 72.726,32.92 126.505,34.295 139.502,34.824 126.505,35.083 127.03,36.578 139.083,36.825 127.03,37.366 140.475,38.162 125.584,38.42 64.097,38.691 66.171,38.68 68.116,38.691 140.475,38.95 61.528,39.094 70.648,39.094 125.584,39.208 64.109,39.431 66.171,39.42 68.116,39.431 101.221,39.634 102.721,39.634 106.381,39.634 107.881,39.634 111.63,39.634 113.13,39.634 116.879,39.634 118.379,39.634 121.875,39.624 123.375,39.624 140.475,39.738 61.528,39.834 70.648,39.834 125.584,39.996 140.475,40.526 125.584,40.784 45.948,40.936 51.614,40.936 57.174,40.936 61.478,40.942 63.774,40.942 66.069,40.942 68.365,40.942 74.77,40.95 80.328,40.991 140.475,41.314 125.584,41.572 45.948,41.968 51.614,41.968 57.174,41.968 74.77,41.982 80.328,42.023 140.475,42.101 60.535,42.228 62.83,42.228 65.126,42.228 67.421,42.228 69.717,42.228 72.013,42.228 125.584,42.36 140.475,42.889 125.584,43.148 38.99,43.387 41.49,43.387 43.99,43.387 46.49,43.387 48.99,43.387 51.49,43.387 53.99,43.387 56.49,43.387 58.99,43.387 61.49,43.387 63.99,43.387 66.49,43.387 68.99,43.387 71.49,43.387 76.286,43.387 140.475,43.677 125.584,43.935 140.475,44.465 125.584,44.723 140.475,45.253 125.584,45.511 37.74,45.887 40.24,45.887 42.74,45.887 45.24,45.887 47.74,45.887 50.24,45.887 52.74,45.887 55.24,45.887 62.74,45.887 65.24,45.887 67.74,45.887 70.24,45.887 72.74,45.887 140.475,46.041 125.584,46.299 106.381,47.81 107.881,47.81 111.63,47.81 113.13,47.81 116.879,47.81 118.379,47.81 121.875,47.81 123.375,47.81 101.295,47.827 102.795,47.827 76.313,48.374 38.99,48.387 41.49,48.387 43.99,48.387 46.49,48.387 48.99,48.387 51.49,48.387 53.99,48.387 56.49,48.387 58.99,48.387 61.49,48.387 63.99,48.387 66.49,48.387 68.99,48.387 71.49,48.387 68.87,50.091 71.165,50.091 73.461,50.091 52.894,50.119 55.189,50.119 57.485,50.119 59.78,50.119 62.076,50.119 64.371,50.119 66.667,50.119 75.757,50.418 54.099,51.077 56.395,51.077 58.69,51.077 60.986,51.077 63.281,51.077 65.577,51.077 67.933,51.077 70.229,51.077 72.524,51.077 74.82,51.077 127.965,51.125 53.094,51.895 55.39,51.895 57.686,51.895 59.981,51.895 62.277,51.895 64.572,51.895 66.868,51.895 68.87,51.893 71.165,51.893 73.461,51.893 75.757,51.893 127.965,51.913 132.101,52.36 134.922,52.36 127.965,52.7 127.965,53.488 127.913,54.36 56.542,54.77 57.298,54.77 65.237,54.772 65.993,54.772 74.089,54.799 74.845,54.799 127.913,55.148 127.913,55.936 62.722,56.372 63.943,56.372 65.061,56.374 66.335,56.372 67.625,56.372 68.795,56.372 54.092,56.456 55.313,56.456 56.43,56.458 57.704,56.456 58.994,56.456 60.165,56.456 71.534,56.459 72.755,56.459 73.872,56.462 75.146,56.459 76.436,56.459 77.607,56.459 31.785,57.334 142.641,62.099 140.486,62.45 144.355,62.45 145.886,62.869 131.245,65.268 58.565,65.589 72.726,65.685 129.249,66.11 131.245,66.768 127.315,66.913 58.49,67.227 72.726,67.329 129.249,67.61 131.245,68.306 127.315,68.413 129.249,69.148 131.245,69.806 127.315,69.951 129.249,70.648 127.315,71.451 131.245,71.536 101.133,72.321 102.633,72.321 106.381,72.321 107.881,72.321 111.63,72.321 113.13,72.321 116.879,72.321 118.379,72.321 121.875,72.336 123.375,72.336 129.249,72.379 131.245,73.036 127.315,73.182 64.232,73.836 66.177,73.835 68.098,73.83 129.249,73.879 61.698,74.119 70.626,74.155 68.116,74.483 64.25,74.489 66.195,74.488 127.315,74.682 61.698,74.86 70.626,74.895 46.268,75.821 51.896,75.821 57.523,75.821 60.986,76.029 74.74,76.015 63.306,76.07 65.602,76.07 67.897,76.07 70.193,76.07 80.279,76.065 46.268,76.611 51.896,76.611 57.502,76.611 101.133,77.018 102.633,77.018 106.381,77.018 107.881,77.018 111.63,77.018 113.13,77.018 116.879,77.018 118.379,77.018 121.875,77.018 123.375,77.018 126.858,77.018 128.358,77.018 74.74,77.081 80.279,77.097 78.424,77.344 55.117,77.372 57.413,77.372 59.708,77.372 62.447,77.372 64.743,77.372 67.039,77.372 69.334,77.372 71.63,77.372 73.925,77.372 76.221,77.372 39.141,77.4 41.437,77.4 43.732,77.4 46.028,77.4 48.323,77.4 50.619,77.4 52.914,77.4 31.173,78.536 33.673,78.536 36.173,78.536 54.832,79.872 57.128,79.872 59.423,79.872 77.752,79.872 80.048,79.872 38.856,79.9 41.151,79.9 43.447,79.9 45.743,79.9 48.038,79.9 50.334,79.9 52.629,79.9 61.776,79.9 64.071,79.9 66.367,79.9 68.662,79.9 70.958,79.9 73.254,79.9 75.549,79.9 137.011,80.018 137.956,80.018 29.923,81.036 32.423,81.036 34.923,81.036 37.423,81.036 39.923,81.036 42.423,81.036 44.923,81.036 47.423,81.036 49.923,81.036 52.423,81.036 54.923,81.036 57.423,81.036 59.923,81.036 62.423,81.036 64.923,81.036 67.423,81.036 69.923,81.036 72.423,81.036 74.923,81.036 77.423,81.036 79.923,81.036 137.011,81.022 137.956,81.022 143.265,81.384 137.011,82.127 143.276,82.218 147.003,82.542 145.369,82.779 31.173,83.536 33.673,83.536 36.173,83.536 38.673,83.536 41.173,83.536 43.673,83.536 46.173,83.536 48.673,83.536 51.173,83.536 53.673,83.536 56.173,83.536 58.673,83.536 61.173,83.536 63.673,83.536 66.173,83.536 68.673,83.536 71.173,83.536 73.673,83.536 76.173,83.536 78.673,83.536 81.173,83.536 137.011,84.19 29.923,86.036 32.423,86.036 34.923,86.036 37.423,86.036 39.923,86.036 42.423,86.036 44.923,86.036 47.423,86.036 49.923,86.036 52.423,86.036 54.923,86.036 57.423,86.036 59.923,86.036 62.423,86.036 64.923,86.036 67.423,86.036 69.923,86.036 72.423,86.036 74.923,86.036 77.423,86.036 79.923,86.036
  other v2: 39.892,17.044 41.092,17.044 42.292,17.044 43.492,17.044 44.692,17.044 39.892,18.244 41.092,18.244 42.292,18.244 43.492,18.244 44.692,18.244 39.892,19.444 41.092,19.444 42.292,19.444 43.492,19.444 44.692,19.444 39.892,20.644 41.092,20.644 42.292,20.644 43.492,20.644 44.692,20.644 39.892,21.844 41.092,21.844 42.292,21.844 43.492,21.844 44.692,21.844 39.892,23.044 41.092,23.044 42.292,23.044 43.492,23.044 44.692,23.044 39.892,51.409 41.092,51.409 42.292,51.409 43.492,51.409 44.692,51.409 39.892,52.609 41.092,52.609 42.292,52.609 43.492,52.609 44.692,52.609 39.892,53.809 41.092,53.809 42.292,53.809 43.492,53.809 44.692,53.809 39.892,55.009 41.092,55.009 42.292,55.009 43.492,55.009 44.692,55.009 39.892,56.209 41.092,56.209 42.292,56.209 43.492,56.209 44.692,56.209 39.892,57.409 41.092,57.409 42.292,57.409 43.492,57.409 44.692,57.409
  other v3: 141.066,70.874 142.206,70.874 143.346,70.874 144.486,70.874 145.626,70.874 139.951,71.829 141.066,71.829 142.206,71.829 143.346,71.829 144.486,71.829 145.626,71.829 146.741,71.829 139.951,73.039 141.066,73.039 142.206,73.039 143.346,73.039 144.486,73.039 145.626,73.039 146.741,73.039 141.066,73.994 142.206,73.994 143.346,73.994 144.486,73.994 145.626,73.994
  other v4: 149.936,67.391 151.707,67.425
HOH_GATE1: R70.1 U3.43 U3.44 U3.45 | length 13
  Top Layer w0.254: U3.45@49.068,29.954 U3.45@49.089,29.933
  Bottom Layer w0.889: v1(51.807,29.322) 54.765,26.364 R70.1@63.563,26.364
  other v1: 50.188,29.322 50.997,29.322
HOH_GATE3: R83.1 U4.43 U4.44 U4.45 | length 15.1
  Top Layer w0.356: U4.45@48.567,64.319 U4.44@48.567,63.684 U4.43@48.567,63.049 49.375,63.049 U4.43@49.378,63.052
  Bottom Layer w0.889: v1(51.737,63.646) 54.695,60.688 R83.1@63.493,60.688
  other v1: 50.118,63.646 50.927,63.646
HOL_GATE1: R68.2 R71.1 U3.46 U3.47 U3.48 | length 11.2
  Bottom Layer w0.889: v1(51.843,31.413) 54.042,29.213 R71.1@62.171,29.213
  other v1: 50.224,31.413 51.033,31.413
HOL_GATE3: R81.2 R84.1 U4.46 U4.47 U4.48 | length 11.2
  Bottom Layer w0.889: v1(51.737,65.684) 53.936,63.485 R84.1@62.065,63.485
  other v1: 50.118,65.684 50.927,65.684
LOH_GATE2: R74.1 R76.1 R78.1 U3.31 U3.32 U3.33 | length 22.3
  Top Layer w0.356: U3.31@48.567,20.429 U3.32@48.567,21.064 U3.33@48.567,21.699
  Bottom Layer w0.889: v1(51.807,21.059) 51.995,20.871 51.995,20.471 53.452,19.013 R74.1@54.274,19.013 R76.1@63.005,19.013 R78.1@71.73,19.013
  other v1: 50.188,21.059 50.997,21.059
LOH_GATE4: R87.1 R89.1 R91.1 U4.31 U4.32 U4.33 | length 23.9
  Top Layer w0.254: U4.31@48.567,54.794 U4.32@48.567,55.429 U4.33@48.567,56.064
  Top Layer w0.356: U4.32@48.567,55.429 U4.32@49.48,55.429
  Bottom Layer w0.889: v1(51.68,55.429) 51.68,53.877 52.227,53.331 R87.1@54.288,53.331 R89.1@62.86,53.331 ; R89.1@62.887,53.331 R91.1@71.612,53.331
  other v1: 50.062,55.429 50.871,55.429
LOL_GATE2: R69.2 R75.1 R77.1 R79.1 U3.34 U3.35 U3.36 | length 18.9
  Bottom Layer w0.889: v1(51.807,23.002) 53.482,23.002 53.568,23.088 60.964,23.088 R77.1@61.464,22.588 ; 61.464,23.088 69.804,23.088 R79.1@70.304,22.588
  other v1: 50.188,23.002 50.997,23.002
LOL_GATE4: R82.2 R88.1 R90.1 R92.1 U4.34 U4.35 U4.36 | length 37.1
  Top Layer w0.356: U4.34@48.567,56.699 U4.35@48.567,57.334 U4.36@48.567,57.969
  Bottom Layer w0.889: v1(51.752,57.406) 51.849,57.503 R92.1@70.218,57.503 ; R88.1@52.918,57.4 61.448,57.4 70.112,57.4 R92.1@70.196,57.316
  other v1: 50.027,57.304 50.836,57.304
